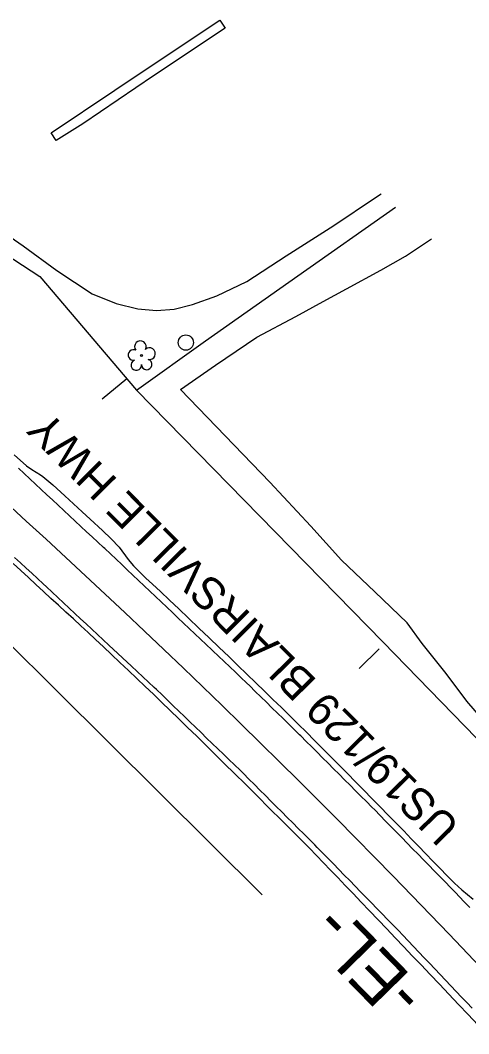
# Model space of a CAD drawing. Extents: x 474972 to 479313, y 498315 to 502691.
# Drawn here: x 477089.8 to 477234.5, y 500160.7 to 500487.8 of the extents above; entities that cross this region are included whole.
import ezdxf

# ---------------------------------------------------------------- set-up
doc = ezdxf.new("R2010")
doc.units = 0
for name, color, linetype in [('Exist Horizontal Alignment', 7, 'Continuous'), ('Exist Horizontal Alignment Direction Label', 7, 'Continuous'), ('Exist Other Culture Fence Line', 7, 'Continuous'), ('Exist Other Culture Sign', 7, 'Continuous'), ('Exist Roads EOP', 7, 'Continuous'), ('Exist Roads EOP Text', 7, 'Continuous'), ('Exist Roads EOT', 7, 'Continuous'), ('Exist Roads Soil', 7, 'Continuous'), ('Exist Structure Minor Paved Ditch or Gutter', 7, 'Continuous'), ('Exist Utilities Other Pole CELL', 7, 'Continuous'), ('Exist Vegetation Tree CELL', 7, 'Continuous'), ('Exist Vegetation Woods Line', 7, 'Continuous')]:
    doc.layers.add(name, color=color, linetype=linetype)

msp = doc.modelspace()

# ---------------------------------------------------------------- linework, layer by layer
at = {"layer": 'Exist Horizontal Alignment'}
msp.add_arc((475159.06, 498211.82), 2864.54, 37.33366, 48.4381, dxfattribs=at)
at = {"layer": 'Exist Other Culture Fence Line'}
for points in [[(477039.4, 500442.07), (477096.14, 500405.12), (477127.29, 500368.44), (477206.77, 500287.2), (477263.29, 500228.94), (477335.66, 500260.31)], [(477127.29, 500368.44), (477149.51, 500384.33), (477179.37, 500405.26), (477210.83, 500427.5)]]:
    msp.add_lwpolyline(points, dxfattribs=at)
at = {"layer": 'Exist Other Culture Sign'}
for p, q in [((477124.18, 500372.03), (477116.18, 500365.52)), ((477205.6, 500284.95), (477199.08, 500278.56))]:
    msp.add_line(p, q, dxfattribs=at)
at = {"layer": 'Exist Roads EOP'}
for points in [[(477087.76, 500347.57), (477091.81, 500344.01), (477093.48, 500342.78), (477096.33, 500341.08), (477097.05, 500340.58), (477100.25, 500337.85), (477104.17, 500334.29), (477106.92, 500331.76), (477109.77, 500329.14), (477112.29, 500326.82), (477116.3, 500323.09), (477119.06, 500320.47), (477121.68, 500317.72), (477124.56, 500313.73), (477126.33, 500311.66), (477130.33, 500307.76), (477132.4, 500305.81), (477134.98, 500303.39), (477137.89, 500300.66), (477140.93, 500297.79), (477144.1, 500294.78), (477147.4, 500291.63), (477150.72, 500288.46), (477153.93, 500285.39), (477157.03, 500282.42), (477160.02, 500279.55), (477162.92, 500276.74), (477165.77, 500273.99), (477168.57, 500271.27), (477171.31, 500268.6), (477174.02, 500265.95), (477176.72, 500263.3), (477179.41, 500260.64), (477182.09, 500257.98), (477184.76, 500255.32), (477187.41, 500252.66), (477190.05, 500250), (477192.68, 500247.34), (477195.31, 500244.67), (477197.94, 500241.99), (477200.59, 500239.29), (477203.25, 500236.58), (477205.89, 500233.89), (477208.48, 500231.25), (477211.02, 500228.67), (477213.5, 500226.13), (477215.94, 500223.65), (477218.32, 500221.2), (477220.64, 500218.8), (477222.91, 500216.44), (477224.94, 500214.32), (477227.71, 500211.44), (477229.87, 500209.28), (477232.26, 500207.11), (477235.93, 500204.1)], [(477237.39, 500163.59), (477234.27, 500166.89), (477231.17, 500170.17), (477228.09, 500173.42), (477225.03, 500176.65), (477222.02, 500179.82), (477219.09, 500182.9), (477216.25, 500185.89), (477213.49, 500188.79), (477210.77, 500191.65), (477208.03, 500194.52), (477205.28, 500197.42), (477202.51, 500200.32), (477199.79, 500203.18), (477197.17, 500205.93), (477194.65, 500208.55), (477192.24, 500211.07), (477189.9, 500213.5), (477187.59, 500215.89), (477185.31, 500218.24), (477183.06, 500220.54), (477180.58, 500223.06), (477177.61, 500226.05), (477174.16, 500229.5), (477170.21, 500233.43), (477166.17, 500237.46), (477162.41, 500241.2), (477158.92, 500244.67), (477155.72, 500247.85), (477152.67, 500250.86), (477149.67, 500253.81), (477146.71, 500256.71), (477143.78, 500259.55), (477140.91, 500262.33), (477138.12, 500265.04), (477135.39, 500267.68), (477132.73, 500270.24), (477130.08, 500272.78), (477127.41, 500275.35), (477124.7, 500277.94), (477121.95, 500280.55), (477119.23, 500283.12), (477116.62, 500285.58), (477114.1, 500287.93), (477111.67, 500290.17), (477109.29, 500292.36), (477106.9, 500294.56), (477104.5, 500296.77), (477102.09, 500298.99), (477099.67, 500301.22), (477097.24, 500303.46), (477094.82, 500305.69), (477092.39, 500307.93), (477089.96, 500310.17), (477087.53, 500312.41)]]:
    msp.add_lwpolyline(points, dxfattribs=at)
at = {"layer": 'Exist Roads EOT'}
for points in [[(477234.85, 500201.4), (477233.13, 500203.21), (477231.41, 500205.02), (477230.36, 500206.13), (477228.61, 500207.92), (477226.86, 500209.7), (477225.11, 500211.49), (477223.36, 500213.27), (477221.61, 500215.06), (477219.87, 500216.85), (477218.12, 500218.63), (477216.37, 500220.42), (477214.62, 500222.21), (477212.87, 500223.99), (477211.12, 500225.78), (477209.37, 500227.56), (477207.62, 500229.35), (477205.88, 500231.14), (477204.13, 500232.92), (477203.24, 500233.83), (477201.48, 500235.6), (477199.71, 500237.36), (477197.94, 500239.13), (477196.18, 500240.9), (477194.41, 500242.67), (477192.64, 500244.44), (477190.88, 500246.21), (477189.11, 500247.98), (477187.34, 500249.75), (477185.58, 500251.52), (477183.81, 500253.28), (477182.05, 500255.05), (477180.28, 500256.82), (477179.91, 500257.19), (477178.12, 500258.94), (477176.34, 500260.69), (477174.55, 500262.44), (477172.76, 500264.18), (477170.98, 500265.93), (477169.19, 500267.68), (477167.4, 500269.43), (477165.61, 500271.18), (477163.83, 500272.93), (477162.8, 500273.93), (477160.99, 500275.66), (477159.18, 500277.38), (477157.37, 500279.11), (477155.56, 500280.84), (477153.75, 500282.56), (477151.95, 500284.29), (477151.57, 500284.64), (477149.76, 500286.36), (477147.94, 500288.08), (477146.12, 500289.79), (477144.3, 500291.51), (477142.49, 500293.23), (477140.67, 500294.94), (477138.85, 500296.66), (477137.03, 500298.38), (477135.22, 500300.09), (477133.4, 500301.81), (477131.58, 500303.53), (477129.76, 500305.24), (477127.95, 500306.96), (477126.13, 500308.68), (477124.31, 500310.39), (477122.5, 500312.11), (477120.68, 500313.83), (477118.86, 500315.54), (477117.04, 500317.26), (477116.66, 500317.62), (477114.84, 500319.32), (477113.01, 500321.03), (477111.18, 500322.73), (477109.35, 500324.44), (477107.53, 500326.15), (477105.7, 500327.85), (477103.87, 500329.56), (477102.04, 500331.26), (477100.21, 500332.97), (477098.39, 500334.67), (477096.56, 500336.38), (477094.73, 500338.08), (477092.9, 500339.79), (477091.08, 500341.49), (477089.25, 500343.2)], [(477235.58, 500168.92), (477233.86, 500170.73), (477232.14, 500172.54), (477230.42, 500174.36), (477228.7, 500176.17), (477226.98, 500177.98), (477225.26, 500179.8), (477223.54, 500181.61), (477221.82, 500183.42), (477220.1, 500185.24), (477218.38, 500187.05), (477216.66, 500188.87), (477214.94, 500190.68), (477213.22, 500192.49), (477211.79, 500194), (477210.04, 500195.79), (477208.29, 500197.58), (477206.55, 500199.37), (477204.8, 500201.16), (477203.06, 500202.95), (477201.31, 500204.74), (477199.57, 500206.53), (477197.82, 500208.32), (477196.07, 500210.11), (477194.33, 500211.9), (477192.58, 500213.69), (477190.84, 500215.48), (477189.09, 500217.27), (477187.34, 500219.06), (477185.6, 500220.84), (477184.78, 500221.69), (477183.01, 500223.45), (477181.24, 500225.22), (477179.47, 500226.98), (477177.7, 500228.75), (477175.93, 500230.51), (477174.16, 500232.28), (477172.39, 500234.05), (477170.62, 500235.81), (477168.85, 500237.58), (477167.08, 500239.34), (477165.31, 500241.11), (477163.54, 500242.87), (477161.77, 500244.64), (477160.69, 500245.72), (477158.9, 500247.46), (477157.1, 500249.19), (477155.3, 500250.93), (477153.5, 500252.67), (477151.71, 500254.41), (477149.91, 500256.14), (477148.11, 500257.88), (477146.31, 500259.62), (477144.52, 500261.36), (477142.72, 500263.1), (477140.92, 500264.83), (477139.12, 500266.57), (477137.33, 500268.31), (477135.53, 500270.05), (477133.73, 500271.78), (477133.01, 500272.48), (477131.18, 500274.19), (477129.35, 500275.89), (477127.52, 500277.6), (477125.69, 500279.3), (477118.38, 500286.12), (477116.55, 500287.83), (477114.72, 500289.53), (477112.9, 500291.24), (477111.07, 500292.94), (477109.24, 500294.65), (477107.41, 500296.36), (477105.58, 500298.06), (477103.75, 500299.77), (477101.92, 500301.47), (477100.1, 500303.18), (477098.27, 500304.88), (477097.16, 500305.91), (477095.32, 500307.6), (477093.48, 500309.29), (477091.64, 500310.98), (477089.8, 500312.68), (477087.95, 500314.37)]]:
    msp.add_lwpolyline(points, dxfattribs=at)
at = {"layer": 'Exist Roads Soil'}
for points in [[(477046.32, 500449.07), (477064.82, 500438.21), (477075.33, 500431.01), (477076.07, 500430.25), (477074.62, 500426.1), (477090.76, 500415.03), (477101.57, 500406.99), (477112.96, 500399.49), (477120.72, 500396.37), (477127.72, 500394.63), (477133.74, 500394.09), (477139.45, 500394.51), (477145.36, 500396.05), (477153.24, 500398.8), (477162.88, 500403.53), (477175.61, 500411.77), (477190.97, 500421.55), (477204.38, 500430.54), (477206.17, 500431.76)], [(477244.67, 500255.5), (477233.83, 500268.08), (477227.18, 500276.96), (477219.43, 500286.67), (477214.66, 500293.27), (477204.23, 500303.37), (477193.47, 500313.52), (477183.5, 500324.49), (477170.34, 500338.69), (477141.46, 500368.58), (477152.77, 500376.52), (477166.09, 500385.49), (477178.71, 500392.18), (477187.47, 500396.97), (477194.99, 500401.13), (477206.13, 500407.17), (477214.03, 500411.66), (477222.44, 500417.22)]]:
    msp.add_lwpolyline(points, dxfattribs=at)
at = {"layer": 'Exist Structure Minor Paved Ditch or Gutter'}
msp.add_lwpolyline([(477099.74, 500451.48), (477120.34, 500465.19), (477145.55, 500482.07), (477154.19, 500487.79), (477155.87, 500485.28), (477132.74, 500469.82), (477109.93, 500454.4), (477101.36, 500449), (477099.74, 500451.48)], dxfattribs=at)
at = {"layer": 'Exist Utilities Other Pole CELL'}
msp.add_circle((477143.19, 500383.76), 2.46, dxfattribs=at)
at = {"layer": 'Exist Vegetation Tree CELL'}
msp.add_line((477128.91, 500379.61), (477128.91, 500379.61), dxfattribs=at)
msp.add_circle((477128.91, 500379.61), 0.326, dxfattribs=at)
for centre, radius, start, end in [((477128.53, 500382.48), 1.86, 330.1651, 219.7134), ((477126.31, 500379.76), 1.73, 62.6636, 279.3457), ((477131.46, 500380.2), 1.9, 257.1011, 134.1999), ((477127.21, 500376.49), 1.69, 111.5671, 6.231), ((477130.59, 500376.71), 1.7, 181.2822, 74.56)]:
    msp.add_arc(centre, radius, start, end, dxfattribs=at)
at = {"layer": 'Exist Vegetation Woods Line'}
msp.add_lwpolyline([(476943.38, 500238.41), (476935.63, 500264.39), (476940.38, 500290.33), (476956.31, 500318.31), (476964.65, 500322.73), (476987.23, 500301.46), (477019.76, 500279.11), (477029.53, 500284.67), (477029.69, 500296.87), (477034.51, 500308.35), (477035.72, 500311.75), (476996.88, 500350.75), (477003.33, 500356.68), (477018.56, 500353.82), (477167.87, 500205.55)], dxfattribs=at)

# ---------------------------------------------------------------- texts
at = {"layer": 'Exist Horizontal Alignment Direction Label'}
msp.add_text('-EL-', height=16, rotation=134.3691, dxfattribs=at).set_placement((477221.07, 500174.27))
at = {"layer": 'Exist Roads EOP Text'}
msp.add_text('US19/129 BLAIRSVILLE HWY', height=10.4, rotation=134.7806, dxfattribs=at).set_placement((477232.1, 500227.93))

doc.saveas('drawing.dxf')
